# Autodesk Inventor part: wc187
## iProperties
Shininess: 64.0
Length Units: 11272
Angle Units: 11279
Time Units: 11290
Mass Units: 11286
Length Display Precision: 3
Angle Display Precision: 2
Compacted: True
Part Number: wc187
Document SubType Name: Modeling
Created: 2004-08
Designer: John Blackburn
Manufacturer: Standard
Standards Organization: Custom
Density: 0.0
Volumn: 0.0
Area: 0.0
PropertySet Name: Model Information
Control State: 0
Master: False
Checked Out: False
Author: John Blackburn
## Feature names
1. Base1
